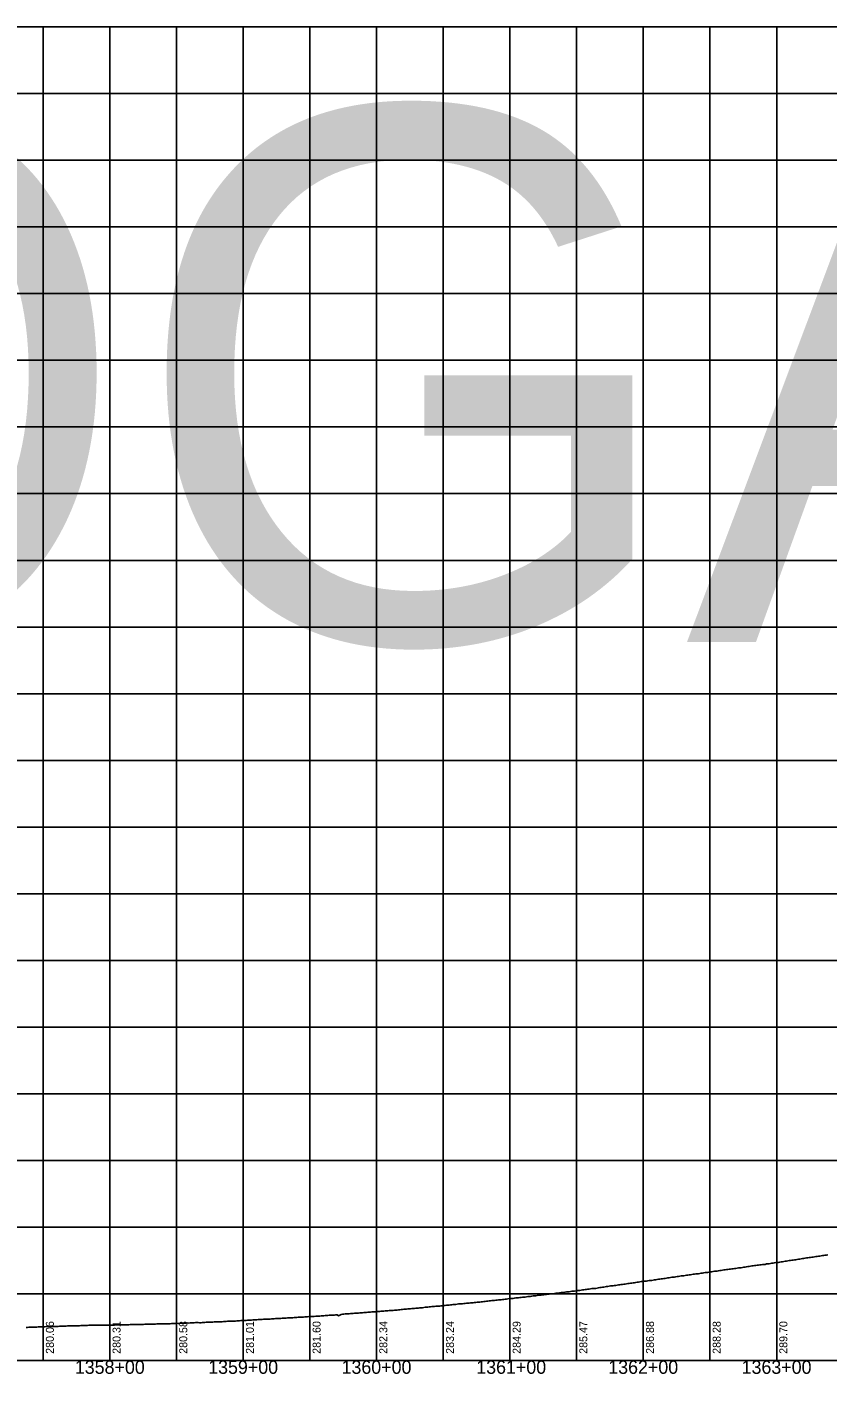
# Model space of a CAD drawing. Extents: x -90830 to 2015517, y -20856 to 836331.
# Drawn here: x 15161 to 15761, y 20053 to 21063 of the extents above; entities that cross this region are included whole.
import ezdxf

# ---------------------------------------------------------------- set-up
doc = ezdxf.new("R2010")
doc.units = 0
for name, color, linetype in [('Level 1', 7, 'Continuous'), ('RD_DDB_Profile_EX', 7, 'Continuous'), ('RD_DDB_StaTX', 7, 'Continuous'), ('RD_DDB_StripGrade', 7, 'Continuous'), ('RD_GPK_Profile_Cell', 7, 'Continuous')]:
    doc.layers.add(name, color=color, linetype=linetype)

msp = doc.modelspace()

# ---------------------------------------------------------------- linework, layer by layer
at = {"layer": 'Level 1'}
for p, q in [((14423.5, 21062.9), (16023.5, 21062.9)), ((15173.5, 21062.9), (15173.5, 20562.9)), ((15223.5, 21062.9), (15223.5, 20562.9)), ((15273.5, 21062.9), (15273.5, 20562.9)), ((15323.5, 21062.9), (15323.5, 20562.9)), ((15373.5, 21062.9), (15373.5, 20562.9)), ((15423.5, 21062.9), (15423.5, 20562.9)), ((15473.5, 21062.9), (15473.5, 20562.9)), ((15523.5, 21062.9), (15523.5, 20562.9)), ((15573.5, 21062.9), (15573.5, 20562.9)), ((15623.5, 21062.9), (15623.5, 20562.9)), ((15673.5, 21062.9), (15673.5, 20562.9)), ((15723.5, 21062.9), (15723.5, 20562.9)), ((14423.5, 21012.9), (16023.5, 21012.9)), ((14423.5, 20962.9), (16023.5, 20962.9)), ((14423.5, 20912.9), (16023.5, 20912.9)), ((14423.5, 20862.9), (16023.5, 20862.9)), ((14423.5, 20812.9), (16023.5, 20812.9)), ((14423.5, 20762.9), (16023.5, 20762.9)), ((14423.5, 20712.9), (16023.5, 20712.9)), ((14423.5, 20662.9), (16023.5, 20662.9)), ((14423.5, 20612.9), (16023.5, 20612.9)), ((14423.5, 20562.9), (16023.5, 20562.9)), ((14423.5, 20562.9), (16023.5, 20562.9)), ((15173.5, 20562.9), (15173.5, 20062.9)), ((15223.5, 20562.9), (15223.5, 20062.9)), ((15273.5, 20562.9), (15273.5, 20062.9)), ((15323.5, 20562.9), (15323.5, 20062.9)), ((15373.5, 20562.9), (15373.5, 20062.9)), ((15423.5, 20562.9), (15423.5, 20062.9)), ((15473.5, 20562.9), (15473.5, 20062.9)), ((15523.5, 20562.9), (15523.5, 20062.9)), ((15573.5, 20562.9), (15573.5, 20062.9)), ((15623.5, 20562.9), (15623.5, 20062.9)), ((15673.5, 20562.9), (15673.5, 20062.9)), ((15723.5, 20562.9), (15723.5, 20062.9)), ((14423.5, 20512.9), (16023.5, 20512.9)), ((14423.5, 20462.9), (16023.5, 20462.9)), ((14423.5, 20412.9), (16023.5, 20412.9)), ((14423.5, 20362.9), (16023.5, 20362.9)), ((14423.5, 20312.9), (16023.5, 20312.9)), ((14423.5, 20262.9), (16023.5, 20262.9)), ((14423.5, 20212.9), (16023.5, 20212.9)), ((14423.5, 20162.9), (16023.5, 20162.9)), ((14423.5, 20112.9), (16023.5, 20112.9)), ((14423.5, 20062.9), (16023.5, 20062.9))]:
    msp.add_line(p, q, dxfattribs=at)
at = {"layer": 'RD_DDB_Profile_EX'}
for points in [[(15636.8, 20124.1), (15637.8, 20124.2), (15638.8, 20124.3), (15639.8, 20124.5), (15640.8, 20124.7), (15641.8, 20124.9), (15642.8, 20125), (15643.8, 20125.1), (15644.8, 20125.3), (15645.8, 20125.5), (15646.8, 20125.5), (15647.8, 20125.7), (15648.8, 20125.8), (15649.8, 20126), (15650.8, 20126.1), (15651.8, 20126.3), (15652.8, 20126.4), (15653.8, 20126.5), (15654.8, 20126.6), (15655.8, 20126.8), (15656.8, 20126.9), (15657.8, 20127.1), (15658.8, 20127.2), (15659.8, 20127.4), (15660.8, 20127.6), (15661.8, 20127.7), (15662.8, 20127.8), (15663.8, 20127.9), (15664.8, 20128), (15665.8, 20128.2), (15666.8, 20128.4), (15667.8, 20128.5), (15668.8, 20128.7), (15669.8, 20128.8), (15670.8, 20128.9), (15671.8, 20129), (15672.8, 20129.2), (15673.8, 20129.3), (15674.8, 20129.5), (15675.8, 20129.7), (15676.8, 20129.8), (15677.8, 20129.9), (15678.8, 20130), (15679.8, 20130.2), (15680.8, 20130.3), (15681.8, 20130.4), (15682.8, 20130.6), (15683.8, 20130.8), (15684.8, 20131), (15685.8, 20131.1), (15686.8, 20131.2), (15687.8, 20131.3), (15688.8, 20131.5), (15689.8, 20131.6), (15690.8, 20131.7), (15691.8, 20131.8), (15692.8, 20132), (15693.8, 20132.1), (15694.8, 20132.3), (15695.8, 20132.4), (15696.8, 20132.5), (15697.8, 20132.7), (15698.8, 20132.9), (15699.8, 20133), (15700.8, 20133.2), (15701.8, 20133.3), (15702.8, 20133.4), (15703.8, 20133.6), (15704.8, 20133.8), (15705.8, 20133.9), (15706.8, 20134.1), (15707.8, 20134.2), (15708.8, 20134.3), (15709.8, 20134.5), (15710.8, 20134.6), (15711.8, 20134.7), (15712.8, 20134.8), (15713.8, 20134.9), (15714.8, 20135), (15715.8, 20135.3), (15716.8, 20135.4), (15717.8, 20135.5), (15718.8, 20135.7), (15719.8, 20135.9), (15720.8, 20136), (15721.8, 20136.2), (15722.8, 20136.3), (15723.8, 20136.4), (15724.8, 20136.5), (15725.8, 20136.7), (15726.8, 20136.8), (15727.8, 20137), (15728.8, 20137.1), (15729.8, 20137.3), (15730.8, 20137.4), (15731.8, 20137.6), (15732.8, 20137.8), (15733.8, 20137.9), (15734.8, 20138.1), (15735.8, 20138.2), (15736.8, 20138.3)], [(15736.8, 20138.3), (15737.8, 20138.5), (15738.8, 20138.7), (15739.8, 20138.8), (15740.8, 20138.9), (15741.8, 20139.1), (15742.8, 20139.3), (15743.8, 20139.5), (15744.8, 20139.7), (15745.8, 20139.8), (15746.8, 20139.9), (15747.8, 20140.1), (15748.8, 20140.2), (15749.8, 20140.3), (15750.8, 20140.4), (15751.8, 20140.6), (15752.8, 20140.8), (15753.8, 20141), (15754.8, 20141.1), (15755.8, 20141.2), (15756.8, 20141.4), (15757.8, 20141.6), (15758.8, 20141.7), (15759.8, 20141.9), (15760.8, 20142), (15761.8, 20142.2)], [(15536.8, 20110.8), (15537.8, 20110.9), (15538.8, 20111), (15539.8, 20111.2), (15540.8, 20111.3), (15541.8, 20111.4), (15542.8, 20111.5), (15543.8, 20111.6), (15544.8, 20111.8), (15545.8, 20111.9), (15546.8, 20112), (15547.8, 20112.1), (15548.8, 20112.2), (15549.8, 20112.3), (15550.8, 20112.5), (15551.8, 20112.6), (15552.8, 20112.7), (15553.8, 20112.8), (15554.8, 20112.9), (15555.8, 20113), (15556.8, 20113.1), (15557.8, 20113.3), (15558.8, 20113.4), (15559.8, 20113.5), (15560.8, 20113.7), (15561.8, 20113.8), (15562.8, 20113.9), (15563.8, 20114), (15564.8, 20114.2), (15565.8, 20114.3), (15566.8, 20114.4), (15567.8, 20114.5), (15568.8, 20114.6), (15569.8, 20114.8), (15570.8, 20114.9), (15571.8, 20115), (15572.8, 20115.1), (15573.8, 20115.3), (15574.8, 20115.4), (15575.8, 20115.5), (15576.8, 20115.6), (15577.8, 20115.8), (15578.8, 20115.9), (15579.8, 20116.1), (15580.8, 20116.2), (15581.8, 20116.4), (15582.8, 20116.5), (15583.8, 20116.6), (15584.8, 20116.8), (15585.8, 20116.9), (15586.8, 20117), (15587.8, 20117), (15588.8, 20117.1), (15589.8, 20117.5), (15590.8, 20117.6), (15591.8, 20117.7), (15592.8, 20117.8), (15593.8, 20118), (15594.8, 20118.2), (15595.8, 20118.4), (15596.8, 20118.5), (15597.8, 20118.6), (15598.8, 20118.8), (15599.8, 20118.9), (15600.8, 20119), (15601.8, 20119.2), (15602.8, 20119.2), (15603.8, 20119.3), (15604.8, 20119.6), (15605.8, 20119.7), (15606.8, 20119.9), (15607.8, 20120), (15608.8, 20120.1), (15609.8, 20120.2), (15610.8, 20120.4), (15611.8, 20120.6), (15612.8, 20120.7), (15613.8, 20120.8), (15614.8, 20121), (15615.8, 20121.1), (15616.8, 20121.2), (15617.8, 20121.5), (15618.8, 20121.6), (15619.8, 20121.7), (15620.8, 20121.8), (15621.8, 20122.1), (15622.8, 20122.1), (15623.8, 20122.3), (15624.8, 20122.4), (15625.8, 20122.5), (15626.8, 20122.7), (15627.8, 20122.8), (15628.8, 20122.9), (15629.8, 20123), (15630.8, 20123.2), (15631.8, 20123.4), (15632.8, 20123.5), (15633.8, 20123.7), (15634.8, 20123.8), (15635.8, 20123.9), (15636.8, 20124.1)], [(15436.8, 20100.6), (15437.8, 20100.7), (15438.8, 20100.7), (15439.8, 20100.8), (15440.8, 20100.9), (15441.8, 20101.1), (15442.8, 20101.2), (15443.8, 20101.3), (15444.8, 20101.3), (15445.8, 20101.5), (15446.8, 20101.6), (15447.8, 20101.6), (15448.8, 20101.7), (15449.8, 20101.8), (15450.8, 20102), (15451.8, 20102), (15452.8, 20102.1), (15453.8, 20102.2), (15454.8, 20102.2), (15455.8, 20102.4), (15456.8, 20102.5), (15457.8, 20102.5), (15458.8, 20102.6), (15459.8, 20102.8), (15460.8, 20102.8), (15461.8, 20103), (15462.8, 20103.1), (15463.8, 20103.2), (15464.8, 20103.3), (15465.8, 20103.3), (15466.8, 20103.5), (15467.8, 20103.6), (15468.8, 20103.6), (15469.8, 20103.6), (15470.8, 20103.7), (15471.8, 20104), (15472.8, 20104), (15473.8, 20104.1), (15474.8, 20104.2), (15475.8, 20104.3), (15476.8, 20104.4), (15477.8, 20104.5), (15478.8, 20104.6), (15479.8, 20104.7), (15480.8, 20104.9), (15481.8, 20104.9), (15482.8, 20105), (15483.8, 20105.1), (15484.8, 20105.3), (15485.8, 20105.4), (15486.8, 20105.4), (15487.8, 20105.5), (15488.8, 20105.6), (15489.8, 20105.7), (15490.8, 20105.8), (15491.8, 20105.9), (15492.8, 20105.9), (15493.8, 20106.1), (15494.8, 20106.1), (15495.8, 20106.2), (15496.8, 20106.4), (15497.8, 20106.5), (15498.8, 20106.6), (15499.8, 20106.7), (15500.8, 20106.7), (15501.8, 20106.8), (15502.8, 20107), (15503.8, 20107.1), (15504.8, 20107.2), (15505.8, 20107.3), (15506.8, 20107.5), (15507.8, 20107.6), (15508.8, 20107.7), (15509.8, 20107.8), (15510.8, 20107.9), (15511.8, 20108), (15512.8, 20108.1), (15513.8, 20108.2), (15514.8, 20108.3), (15515.8, 20108.4), (15516.8, 20108.5), (15517.8, 20108.6), (15518.8, 20108.7), (15519.8, 20108.8), (15520.8, 20109), (15521.8, 20109.1), (15522.8, 20109.3), (15523.8, 20109.4), (15524.8, 20109.4), (15525.8, 20109.5), (15526.8, 20109.7), (15527.8, 20109.8), (15528.8, 20109.9), (15529.8, 20110), (15530.8, 20110.1), (15531.8, 20110.2), (15532.8, 20110.3), (15533.8, 20110.4), (15534.8, 20110.5), (15535.8, 20110.6), (15536.8, 20110.8)], [(15236.8, 20089.6), (15237.8, 20089.7), (15238.8, 20089.8), (15239.8, 20089.8), (15240.8, 20089.9), (15241.8, 20089.9), (15242.8, 20089.9), (15243.8, 20089.9), (15244.8, 20089.9), (15245.8, 20089.9), (15246.8, 20090), (15247.8, 20090), (15248.8, 20090), (15249.8, 20090.1), (15250.8, 20090.1), (15251.8, 20090.1), (15252.8, 20090.1), (15253.8, 20090.2), (15254.8, 20090.2), (15255.8, 20090.2), (15256.8, 20090.2), (15257.8, 20090.2), (15258.8, 20090.3), (15259.8, 20090.3), (15260.8, 20090.4), (15261.8, 20090.4), (15262.8, 20090.4), (15263.8, 20090.4), (15264.8, 20090.5), (15265.8, 20090.5), (15266.8, 20090.5), (15267.8, 20090.4), (15268.8, 20090.5), (15269.8, 20090.6), (15270.8, 20090.6), (15271.8, 20090.7), (15272.8, 20090.7), (15273.8, 20090.8), (15274.8, 20090.7), (15275.8, 20090.7), (15276.8, 20090.8), (15277.8, 20090.8), (15278.8, 20090.8), (15279.8, 20090.9), (15280.8, 20091), (15281.8, 20091.1), (15282.8, 20091), (15283.8, 20091.1), (15284.8, 20091.1), (15285.8, 20091.2), (15286.8, 20091.2), (15287.8, 20091.3), (15288.8, 20091.3), (15289.8, 20091.3), (15290.8, 20091.2), (15291.8, 20091.1), (15292.8, 20091.4), (15293.8, 20091.5), (15294.8, 20091.5), (15295.8, 20091.6), (15296.8, 20091.6), (15297.8, 20091.7), (15298.8, 20091.7), (15299.8, 20091.7), (15300.8, 20091.7), (15301.8, 20091.8), (15302.8, 20091.8), (15303.8, 20091.9), (15304.8, 20091.9), (15305.8, 20091.9), (15306.8, 20092), (15307.8, 20092), (15308.8, 20092.1), (15309.8, 20092.2), (15310.8, 20092.2), (15311.8, 20092.3), (15312.8, 20092.3), (15313.8, 20092.3), (15314.8, 20092.4), (15315.8, 20092.5), (15316.8, 20092.5), (15317.8, 20092.5), (15318.8, 20092.6), (15319.8, 20092.7), (15320.8, 20092.7), (15321.8, 20092.8), (15322.8, 20092.9), (15323.8, 20092.9), (15324.8, 20092.9), (15325.8, 20093), (15326.8, 20093.1), (15327.8, 20093.1), (15328.8, 20093.2), (15329.8, 20093.2), (15330.8, 20093.3), (15331.8, 20093.3), (15332.8, 20093.4), (15333.8, 20093.5), (15334.8, 20093.6), (15335.8, 20093.6), (15336.8, 20093.6)], [(15336.8, 20093.6), (15337.8, 20093.7), (15338.8, 20093.8), (15339.8, 20093.8), (15340.8, 20093.8), (15341.8, 20093.9), (15342.8, 20094), (15343.8, 20094), (15344.8, 20094.1), (15345.8, 20094.2), (15346.8, 20094.2), (15347.8, 20094.3), (15348.8, 20094.4), (15349.8, 20094.4), (15350.8, 20094.5), (15351.8, 20094.5), (15352.8, 20094.6), (15353.8, 20094.7), (15354.8, 20094.7), (15355.8, 20094.7), (15356.8, 20094.8), (15357.8, 20094.9), (15358.8, 20094.9), (15359.8, 20095), (15360.8, 20095), (15361.8, 20095.1), (15362.8, 20095.2), (15363.8, 20095.2), (15364.8, 20095.3), (15365.8, 20095.3), (15366.8, 20095.4), (15367.8, 20095.4), (15368.8, 20095.5), (15369.8, 20095.6), (15370.8, 20095.7), (15371.8, 20095.7), (15372.8, 20095.8), (15373.8, 20095.9), (15374.8, 20095.9), (15375.8, 20095.9), (15376.8, 20096), (15377.8, 20096.1), (15378.8, 20096.1), (15379.8, 20096.2), (15380.8, 20096.2), (15381.8, 20096.3), (15382.8, 20096.4), (15383.8, 20096.5), (15384.8, 20096.6), (15385.8, 20096.6), (15386.8, 20096.7), (15387.8, 20096.8), (15388.8, 20096.9), (15389.8, 20097), (15390.8, 20097), (15391.8, 20097), (15392.8, 20097.2), (15393.8, 20097.1), (15394.8, 20096.5), (15395.8, 20096.8), (15396.8, 20097.5), (15397.8, 20097.6), (15398.8, 20097.7), (15399.8, 20097.8), (15400.8, 20097.9), (15401.8, 20097.9), (15402.8, 20098), (15403.8, 20098.1), (15404.8, 20098.2), (15405.8, 20098.2), (15406.8, 20098.3), (15407.8, 20098.4), (15408.8, 20098.4), (15409.8, 20098.5), (15410.8, 20098.6), (15411.8, 20098.6), (15412.8, 20098.7), (15413.8, 20098.8), (15414.8, 20098.9), (15415.8, 20099), (15416.8, 20099.1), (15417.8, 20099.1), (15418.8, 20099.1), (15419.8, 20099.3), (15420.8, 20099.4), (15421.8, 20099.5), (15422.8, 20099.5), (15423.8, 20099.6), (15424.8, 20099.7), (15425.8, 20099.7), (15426.8, 20099.9), (15427.8, 20100), (15428.8, 20100), (15429.8, 20100.1), (15430.8, 20100.1), (15431.8, 20100.2), (15432.8, 20100.3), (15433.8, 20100.4), (15434.8, 20100.5), (15435.8, 20100.5), (15436.8, 20100.6)], [(15160.8, 20087.7), (15161.8, 20087.7), (15162.8, 20087.8), (15163.8, 20087.8), (15164.8, 20087.8), (15165.8, 20087.9), (15166.8, 20088), (15167.8, 20088), (15168.8, 20088), (15169.8, 20088.1), (15170.8, 20088.1), (15171.8, 20088.1), (15172.8, 20088.2), (15173.8, 20088.2), (15174.8, 20088.2), (15175.8, 20088.3), (15176.8, 20088.3), (15177.8, 20088.3), (15178.8, 20088.4), (15179.8, 20088.4), (15180.8, 20088.4), (15181.8, 20088.4), (15182.8, 20088.5), (15183.8, 20088.5), (15184.8, 20088.5), (15185.8, 20088.6), (15186.8, 20088.6), (15187.8, 20088.6), (15188.8, 20088.7), (15189.8, 20088.7), (15190.8, 20088.7), (15191.8, 20088.8), (15192.8, 20088.8), (15193.8, 20088.8), (15194.8, 20088.8), (15195.8, 20088.9), (15196.8, 20088.9), (15197.8, 20088.9), (15198.8, 20089), (15199.8, 20089), (15200.8, 20089), (15201.8, 20089.1), (15202.8, 20089.1), (15203.8, 20089.1), (15204.8, 20089.2), (15205.8, 20089.2), (15206.8, 20089.2), (15207.8, 20089.3), (15208.8, 20089.3), (15209.8, 20089.3), (15210.8, 20089.3), (15211.8, 20089.3), (15212.8, 20089.3), (15213.8, 20089.3), (15214.8, 20089.4), (15215.8, 20089.3), (15216.8, 20089.3), (15217.8, 20089.3), (15218.8, 20089.4), (15219.8, 20089.4), (15220.8, 20089.5), (15221.8, 20089.4), (15222.8, 20089.4), (15223.8, 20089.4), (15224.8, 20089.4), (15225.8, 20089.5), (15226.8, 20089.5), (15227.8, 20089.6), (15228.8, 20089.6), (15229.8, 20089.6), (15230.8, 20089.6), (15231.8, 20089.6), (15232.8, 20089.7), (15233.8, 20089.7), (15234.8, 20089.7), (15235.8, 20089.6), (15236.8, 20089.6)]]:
    msp.add_lwpolyline(points, dxfattribs=at)
at = {"layer": 'RD_GPK_Profile_Cell'}
msp.add_line((14436.8, 20062.9), (16636.8, 20062.9), dxfattribs=at)

# ---------------------------------------------------------------- texts
at = {"layer": 'RD_DDB_StaTX'}
for s, p in [('1358+00', (15197.2, 20052.9)), ('1359+00', (15297.2, 20052.9)), ('1360+00', (15397.2, 20052.9)), ('1361+00', (15498.2, 20052.9)), ('1362+00', (15597.2, 20052.9)), ('1363+00', (15697.2, 20052.9))]:
    msp.add_text(s, height=10, dxfattribs=at).set_placement(p)
at = {"layer": 'RD_DDB_StripGrade'}
for s, p in [('280.06', (15181.5, 20067.9)), ('280.31', (15231.5, 20067.9)), ('280.58', (15281.5, 20067.9)), ('281.01', (15331.5, 20067.9)), ('281.60', (15381.5, 20067.9)), ('282.34', (15431.5, 20067.9)), ('283.24', (15481.5, 20067.9)), ('284.29', (15531.5, 20067.9)), ('285.47', (15581.5, 20067.9)), ('286.88', (15631.5, 20067.9)), ('288.28', (15681.5, 20067.9)), ('289.70', (15731.5, 20067.9))]:
    msp.add_text(s, height=6, rotation=90, dxfattribs=at).set_placement(p)
at = {"layer": 'RD_GPK_Profile_Cell'}
msp.add_text('NOGAP', height=400, dxfattribs=at).set_placement((14436.8, 20601.6))

doc.saveas('drawing.dxf')
